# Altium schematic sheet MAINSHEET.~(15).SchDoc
size 594 x 420 mm; Scale: 1:1; Разраб.: Иванов; Обозначение документа: АБВГ.123456.001 Э3; Пров.: Петров; Утв.: Сидоров; Наименование организации: ОАО "Концерн "МПО-Гидроприбор"; Перв. применение: АБВГ.123456.000; Наименование изделия 1: Плата; Наименование изделия 2: Схема электрическая; Наименование изделия 3: принципиальная; Нач. отд.: Нач. отд.; Фамилия нач. отд.: Сидоров
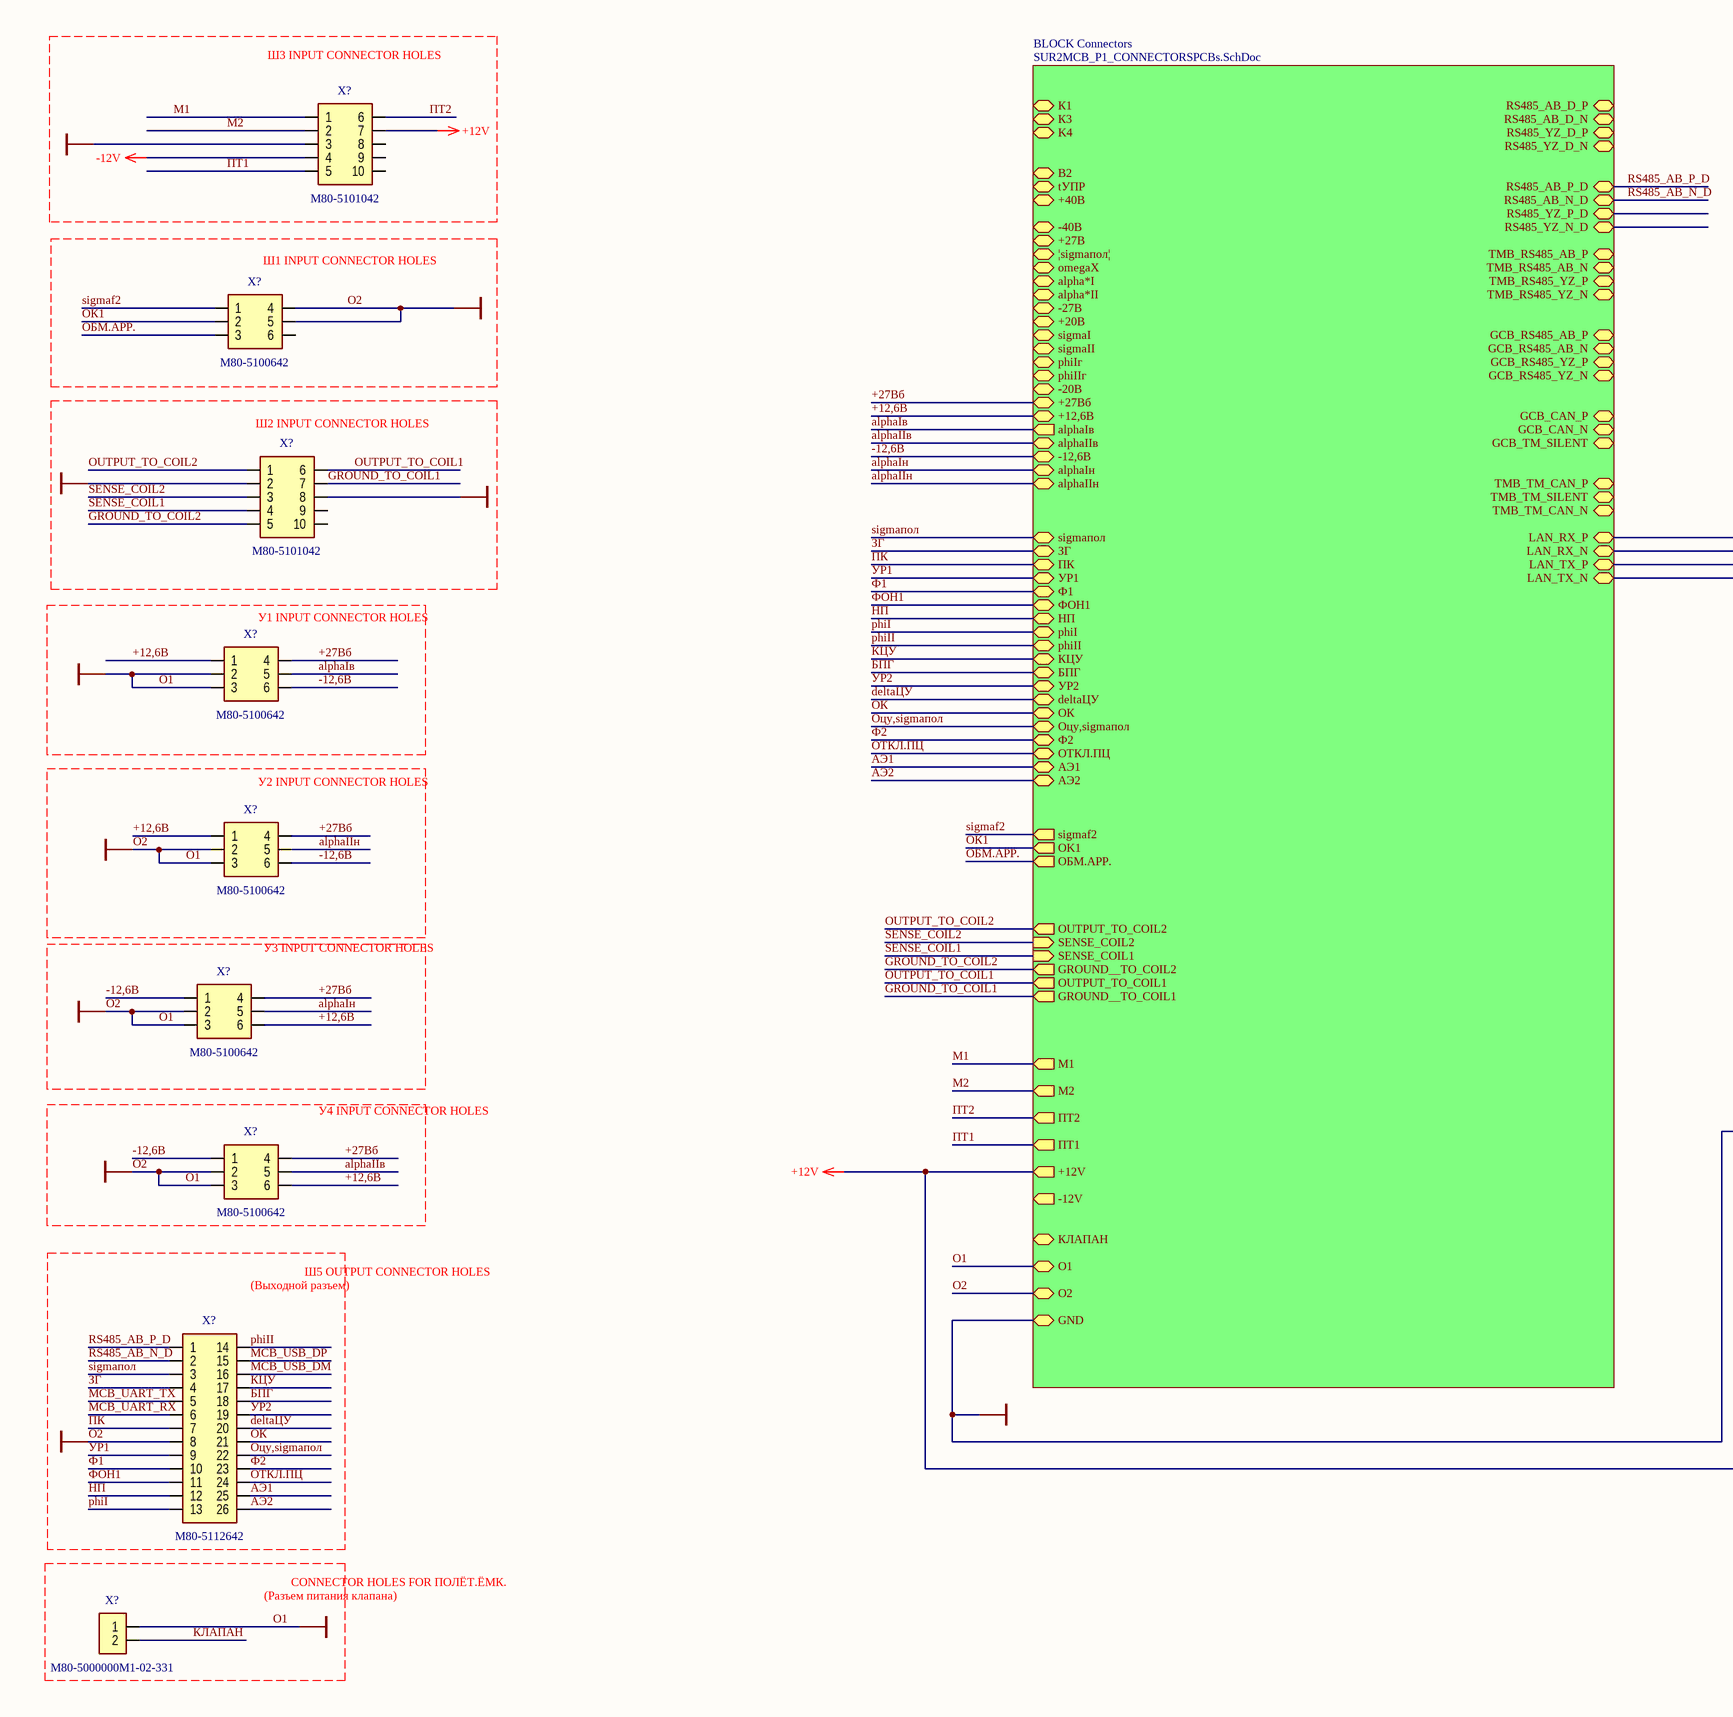
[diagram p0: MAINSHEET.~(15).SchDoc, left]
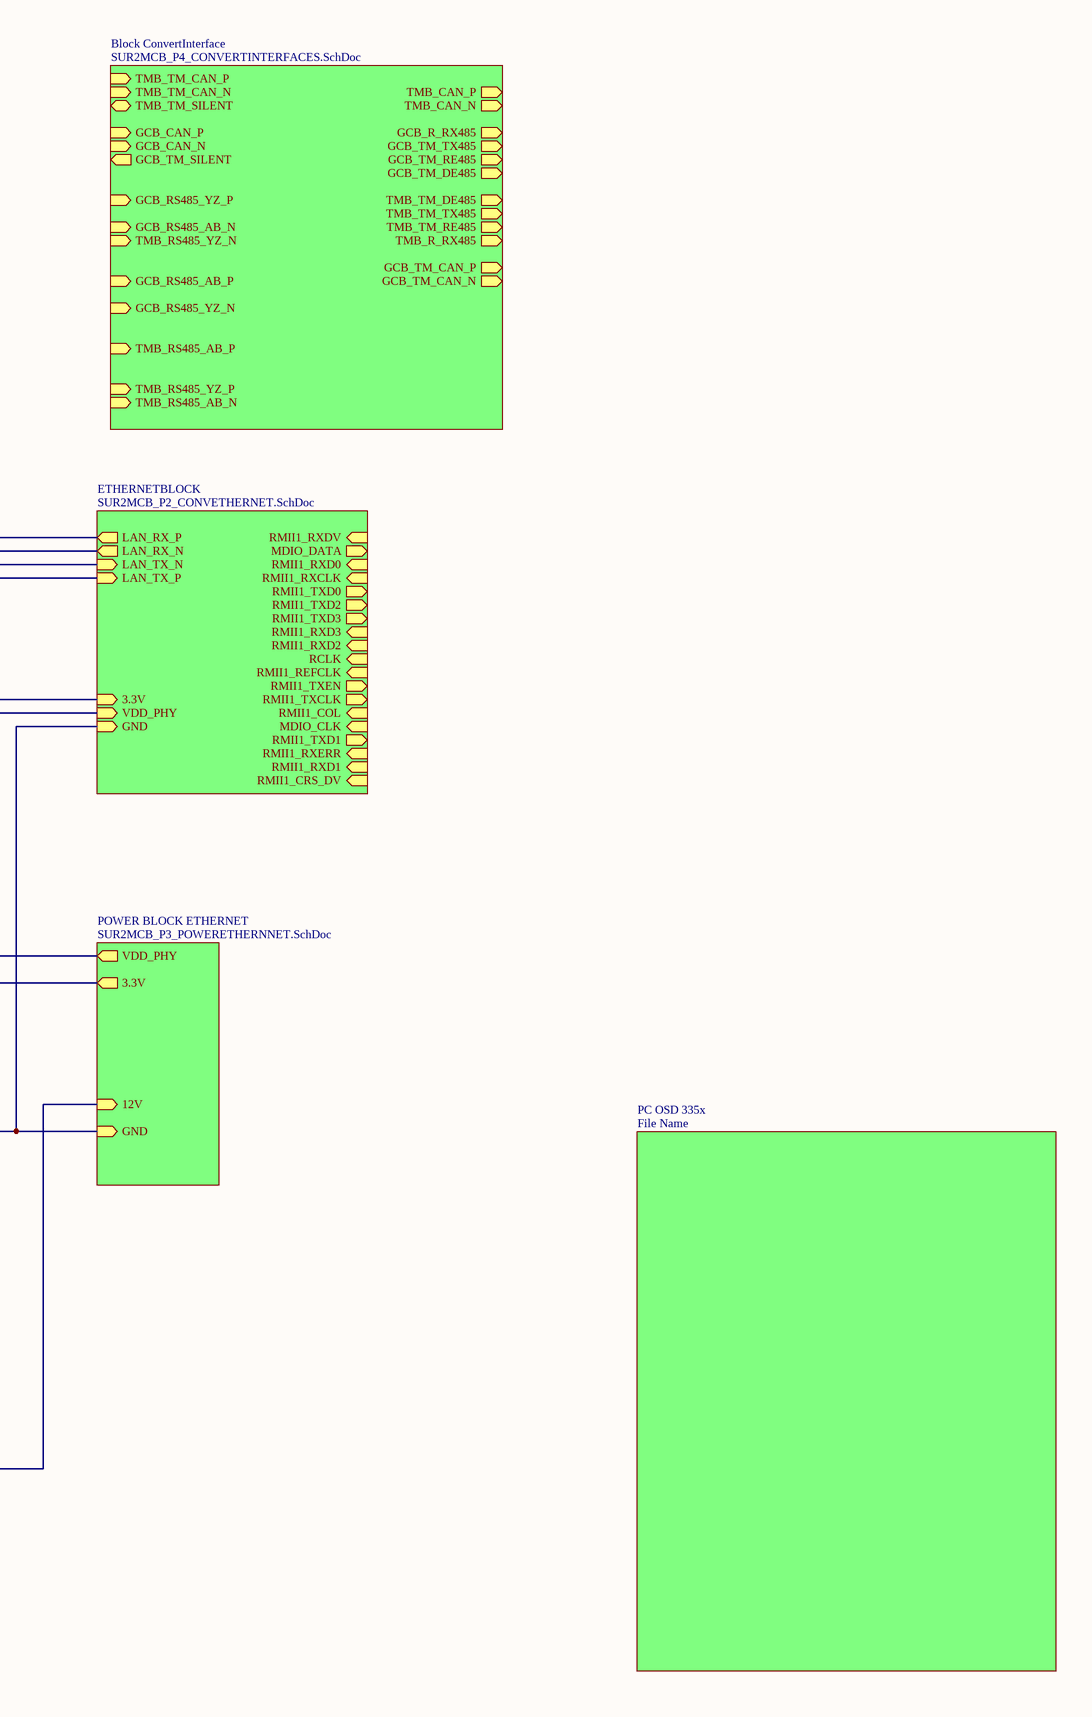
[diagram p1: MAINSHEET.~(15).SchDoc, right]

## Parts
(Parts that share a designator on the sheet are numbered #1, #2 ... from top to bottom, then left to right.)
X?#1  value M80-5101042  [M80-5101042]
X?#2  value M80-5100642  [M80-5100642]
X?#3  value M80-5101042  [M80-5101042]
X?#4  value M80-5100642  [M80-5100642]
X?#5  value M80-5100642  [M80-5100642]
X?#6  value M80-5100642  [M80-5100642]
X?#7  value M80-5100642  [M80-5100642]
X?#8  value M80-5112642  [M80-5112642_HOR]
X?#9  value M80-5000000M1-02-331  [M80-5000000M1-02-331]

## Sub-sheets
BLOCK Connectors = SUR2MCB_P1_CONNECTORSPCBs.SchDoc: tУПР (bidir), B2 (bidir), K4 (bidir), +40В (bidir), К1 (bidir), К3 (bidir), OUTPUT_TO_COIL2 (out), OUTPUT_TO_COIL1 (out), GROUND__TO_COIL1 (out), SENSE_COIL2 (in), GROUND__TO_COIL2 (out), SENSE_COIL1 (in), RS485_YZ_D_N (bidir), RS485_YZ_D_P (bidir), RS485_AB_D_N (bidir), M1 (out), RS485_AB_D_P (bidir), RS485_YZ_N_D (bidir), КЛАПАН (bidir), О1 (bidir), O2 (bidir), RS485_AB_P_D (bidir), RS485_AB_N_D (bidir), RS485_YZ_P_D (bidir), TMB_RS485_AB_N (bidir), TMB_RS485_AB_P (bidir), TMB_RS485_YZ_N (bidir), TMB_RS485_YZ_P (bidir), LAN_RX_P (bidir), LAN_RX_N (bidir), LAN_TX_P (bidir), LAN_TX_N (bidir), GCB_RS485_AB_N (bidir), GCB_RS485_YZ_N (bidir), GCB_RS485_YZ_P (bidir), GCB_RS485_AB_P (bidir), GCB_CAN_P (bidir), GCB_CAN_N (bidir), GCB_TM_SILENT (bidir), TMB_TM_CAN_P (bidir), TMB_TM_SILENT (bidir), TMB_TM_CAN_N (bidir), -40В (bidir), +27В (bidir), ¦sigmaпол¦ (bidir), omegaX (bidir), alpha*II (bidir), alpha*I (bidir), -27В (bidir), +20В (bidir), -20В (bidir), sigmaII (bidir), sigmaI (bidir), phiIIг (bidir), phiIг (bidir), +27Вб (bidir), +12,6В (bidir), -12,6В (bidir), alphaIв (out), alphaIIв (bidir), alphaIIн (bidir), alphaIн (bidir), sigmaпол (bidir), ЗГ (bidir), ПК (bidir), УР1 (bidir), Ф1 (bidir), ФОН1 (bidir), НП (bidir), phiI (bidir), phiII (bidir), ПТ2 (out), +12V (out), КЦУ (bidir), БПГ (bidir), УР2 (bidir), deltaЦУ (bidir), ОК (bidir), Оцу,sigmaпол (bidir), Ф2 (bidir), ОТКЛ.ПЦ (bidir), АЭ1 (bidir), АЭ2 (bidir), ПТ1 (out), M2 (out), -12V (out), sigmaf2 (out), OK1 (out), ОБМ.АРР. (out), GND (bidir)
Block ConvertInterface = SUR2MCB_P4_CONVERTINTERFACES.SchDoc: TMB_TM_TX485 (out), GCB_RS485_YZ_P (in), TMB_R_RX485 (out), GCB_RS485_YZ_N (in), GCB_RS485_AB_P (in), TMB_TM_RE485 (out), GCB_TM_CAN_P (out), TMB_TM_DE485 (out), GCB_TM_CAN_N (out), GCB_RS485_AB_N (in), TMB_RS485_YZ_N (in), GCB_TM_RE485 (out), GCB_CAN_P (in), GCB_R_RX485 (out), GCB_TM_TX485 (out), TMB_RS485_AB_P (in), GCB_TM_SILENT (out), GCB_CAN_N (in), TMB_RS485_YZ_P (in), TMB_RS485_AB_N (in), GCB_TM_DE485 (out), TMB_TM_SILENT (bidir), TMB_TM_CAN_P (in), TMB_TM_CAN_N (in), TMB_CAN_P (out), TMB_CAN_N (out)
ETHERNETBLOCK = SUR2MCB_P2_CONVETHERNET.SchDoc: RMII1_RXDV (in), MDIO_DATA (out), RMII1_RXD0 (in), RMII1_RXCLK (in), RMII1_TXD0 (out), RMII1_TXD2 (out), RMII1_TXD3 (out), RMII1_RXD3 (in), RMII1_RXD2 (in), LAN_RX_P (out), RCLK (in), LAN_RX_N (out), LAN_TX_N (in), RMII1_REFCLK (in), RMII1_TXEN (out), LAN_TX_P (in), RMII1_TXCLK (out), RMII1_COL (in), MDIO_CLK (in), RMII1_TXD1 (out), GND (in), VDD_PHY (in), 3.3V (in), RMII1_RXERR (in), RMII1_RXD1 (in), RMII1_CRS_DV (in)
PC OSD 335x = File Name: no entries
POWER BLOCK ETHERNET = SUR2MCB_P3_POWERETHERNNET.SchDoc: 12V (in), VDD_PHY (out), 3.3V (out), GND (in)

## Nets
+12V: X?#1.7 ; sheet BLOCK Connectors/+12V, sheet POWER BLOCK ETHERNET/12V
-12V: X?#1.4
О1: X?#1.3 X?#2.4 X?#2.5 X?#3.2 X?#3.8 X?#4.2 X?#4.3 X?#5.2 X?#5.3 X?#6.2 X?#6.3 X?#7.2 X?#7.3 X?#8.8 X?#9.1 ; sheet BLOCK Connectors/О1, sheet BLOCK Connectors/O2, sheet BLOCK Connectors/GND, sheet ETHERNETBLOCK/GND, sheet POWER BLOCK ETHERNET/GND  [also labelled GND, О2]
+12,6В: X?#4.1 X?#5.1 X?#6.6 X?#7.6 ; sheet BLOCK Connectors/+12,6В
+27Вб: X?#4.4 X?#5.4 X?#6.4 X?#7.4 ; sheet BLOCK Connectors/+27Вб
-12,6В: X?#4.6 X?#5.6 X?#6.1 X?#7.1 ; sheet BLOCK Connectors/-12,6В
alphaIIв: X?#7.5 ; sheet BLOCK Connectors/alphaIIв
alphaIIн: X?#5.5 ; sheet BLOCK Connectors/alphaIIн
alphaIв: X?#4.5 ; sheet BLOCK Connectors/alphaIв
alphaIн: X?#6.5 ; sheet BLOCK Connectors/alphaIн
deltaЦУ: X?#8.20 ; sheet BLOCK Connectors/deltaЦУ
GROUND_TO_COIL1: X?#3.7 ; sheet BLOCK Connectors/GROUND__TO_COIL1
GROUND_TO_COIL2: X?#3.5 ; sheet BLOCK Connectors/GROUND__TO_COIL2
MCB_UART_RX: X?#8.6
MCB_UART_TX: X?#8.5
MCB_USB_DM: X?#8.16
MCB_USB_DP: X?#8.15
OUTPUT_TO_COIL1: X?#3.6 ; sheet BLOCK Connectors/OUTPUT_TO_COIL1
OUTPUT_TO_COIL2: X?#3.1 ; sheet BLOCK Connectors/OUTPUT_TO_COIL2
phiI: X?#8.13 ; sheet BLOCK Connectors/phiI
phiII: X?#8.14 ; sheet BLOCK Connectors/phiII
RS485_AB_N_D: X?#8.2 ; sheet BLOCK Connectors/RS485_AB_N_D
RS485_AB_P_D: X?#8.1 ; sheet BLOCK Connectors/RS485_AB_P_D
SENSE_COIL1: X?#3.4 ; sheet BLOCK Connectors/SENSE_COIL1
SENSE_COIL2: X?#3.3 ; sheet BLOCK Connectors/SENSE_COIL2
sigmaf2: X?#2.1 ; sheet BLOCK Connectors/sigmaf2
sigmaпол: X?#8.3 ; sheet BLOCK Connectors/sigmaпол
АЭ1: X?#8.25 ; sheet BLOCK Connectors/АЭ1
АЭ2: X?#8.26 ; sheet BLOCK Connectors/АЭ2
БПГ: X?#8.18 ; sheet BLOCK Connectors/БПГ
ЗГ: X?#8.4 ; sheet BLOCK Connectors/ЗГ
КЛАПАН: X?#9.2
КЦУ: X?#8.17 ; sheet BLOCK Connectors/КЦУ
М1: X?#1.1 ; sheet BLOCK Connectors/M1
М2: X?#1.2 ; sheet BLOCK Connectors/M2
НП: X?#8.12 ; sheet BLOCK Connectors/НП
ОБМ.АРР.: X?#2.3 ; sheet BLOCK Connectors/ОБМ.АРР.
ОК: X?#8.21 ; sheet BLOCK Connectors/ОК
ОК1: X?#2.2 ; sheet BLOCK Connectors/OK1
ОТКЛ.ПЦ: X?#8.24 ; sheet BLOCK Connectors/ОТКЛ.ПЦ
Оцу,sigmaпол: X?#8.22 ; sheet BLOCK Connectors/Оцу,sigmaпол
ПК: X?#8.7 ; sheet BLOCK Connectors/ПК
ПТ1: X?#1.5 ; sheet BLOCK Connectors/ПТ1
ПТ2: X?#1.6 ; sheet BLOCK Connectors/ПТ2
УР1: X?#8.9 ; sheet BLOCK Connectors/УР1
УР2: X?#8.19 ; sheet BLOCK Connectors/УР2
Ф1: X?#8.10 ; sheet BLOCK Connectors/Ф1
Ф2: X?#8.23 ; sheet BLOCK Connectors/Ф2
ФОН1: X?#8.11 ; sheet BLOCK Connectors/ФОН1
(unnamed): sheet BLOCK Connectors/LAN_RX_P, sheet ETHERNETBLOCK/LAN_RX_P
(unnamed): sheet BLOCK Connectors/LAN_RX_N, sheet ETHERNETBLOCK/LAN_RX_N  [a separate net that carries the same name]
(unnamed): sheet BLOCK Connectors/LAN_TX_P, sheet ETHERNETBLOCK/LAN_TX_N  [a separate net that carries the same name]
(unnamed): sheet BLOCK Connectors/LAN_TX_N, sheet ETHERNETBLOCK/LAN_TX_P  [a separate net that carries the same name]
(unnamed): sheet ETHERNETBLOCK/VDD_PHY, sheet POWER BLOCK ETHERNET/VDD_PHY  [a separate net that carries the same name]
(unnamed): sheet ETHERNETBLOCK/3.3V, sheet POWER BLOCK ETHERNET/3.3V  [a separate net that carries the same name]

Not connected (* = marked no-connect by the designer): X?#1 8 9 10; X?#2 6; X?#3 9 10

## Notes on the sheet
- Ш3 INPUT CONNECTOR HOLES
- (near X?#2) Ш1 INPUT CONNECTOR HOLES
- (near X?#3) Ш2 INPUT CONNECTOR HOLES
- (near X?#4) У1 INPUT CONNECTOR HOLES
- (near X?#5) У2 INPUT CONNECTOR HOLES
- (near X?#6) У3 INPUT CONNECTOR HOLES
- (near X?#7) У4 INPUT CONNECTOR HOLES
- (Выходной разъем)
- Ш5 OUTPUT CONNECTOR HOLES
- (near X?#9) CONNECTOR HOLES FOR ПОЛЁТ.ЁМК.
- (near X?#9) (Разъем питания клапана)

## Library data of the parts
X?#1 X?#3 = M80-5101042: J-TEK 10 POS DIL MALE 2.0MM 2.2A 800V; ValueManufacturer: Harvin Inc.; PowerVoltage: 2.2A, 800V; ValueDescription: M80-5101042 Вилка Harvin Inc.  6.05x20.4mm  2.2A, 800V; ValueType: Connector
X?#2 X?#4-X?#7 = M80-5100642: J-TEK 6 POS DIL MALE 2.0MM 2.2A 800V; ValueManufacturer: Harvin Inc.; PowerVoltage: 2.2A, 800V; ValueDescription: M80-5100642 Вилка Harvin Inc.  6.05x16.4mm  2.2A, 800V; ValueType: Connector
X?#8 = M80-5112642_HOR: J-TEK 26 POS DIL MALE 2.0MM 2.2A 800V; ValueManufacturer: Harvin Inc.; PowerVoltage: 2.2A, 800V; ValueDescription: M80-5112642 Вилка Harvin Inc.  6.05x36mm  2.2A, 800V; ValueType: Connector
X?#9 = M80-5000000M1-02-331: MIX-TEK 2 POS DIL MALE 4.0MM 20A 600V; ValueManufacturer: Harvin Inc.; PowerVoltage: 20A, 600V; ValueDescription: M80-5000000M1-02-331 Вилка Harvin Inc.  6.05x18.4mm  20A, 600V; ValueType: Connector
